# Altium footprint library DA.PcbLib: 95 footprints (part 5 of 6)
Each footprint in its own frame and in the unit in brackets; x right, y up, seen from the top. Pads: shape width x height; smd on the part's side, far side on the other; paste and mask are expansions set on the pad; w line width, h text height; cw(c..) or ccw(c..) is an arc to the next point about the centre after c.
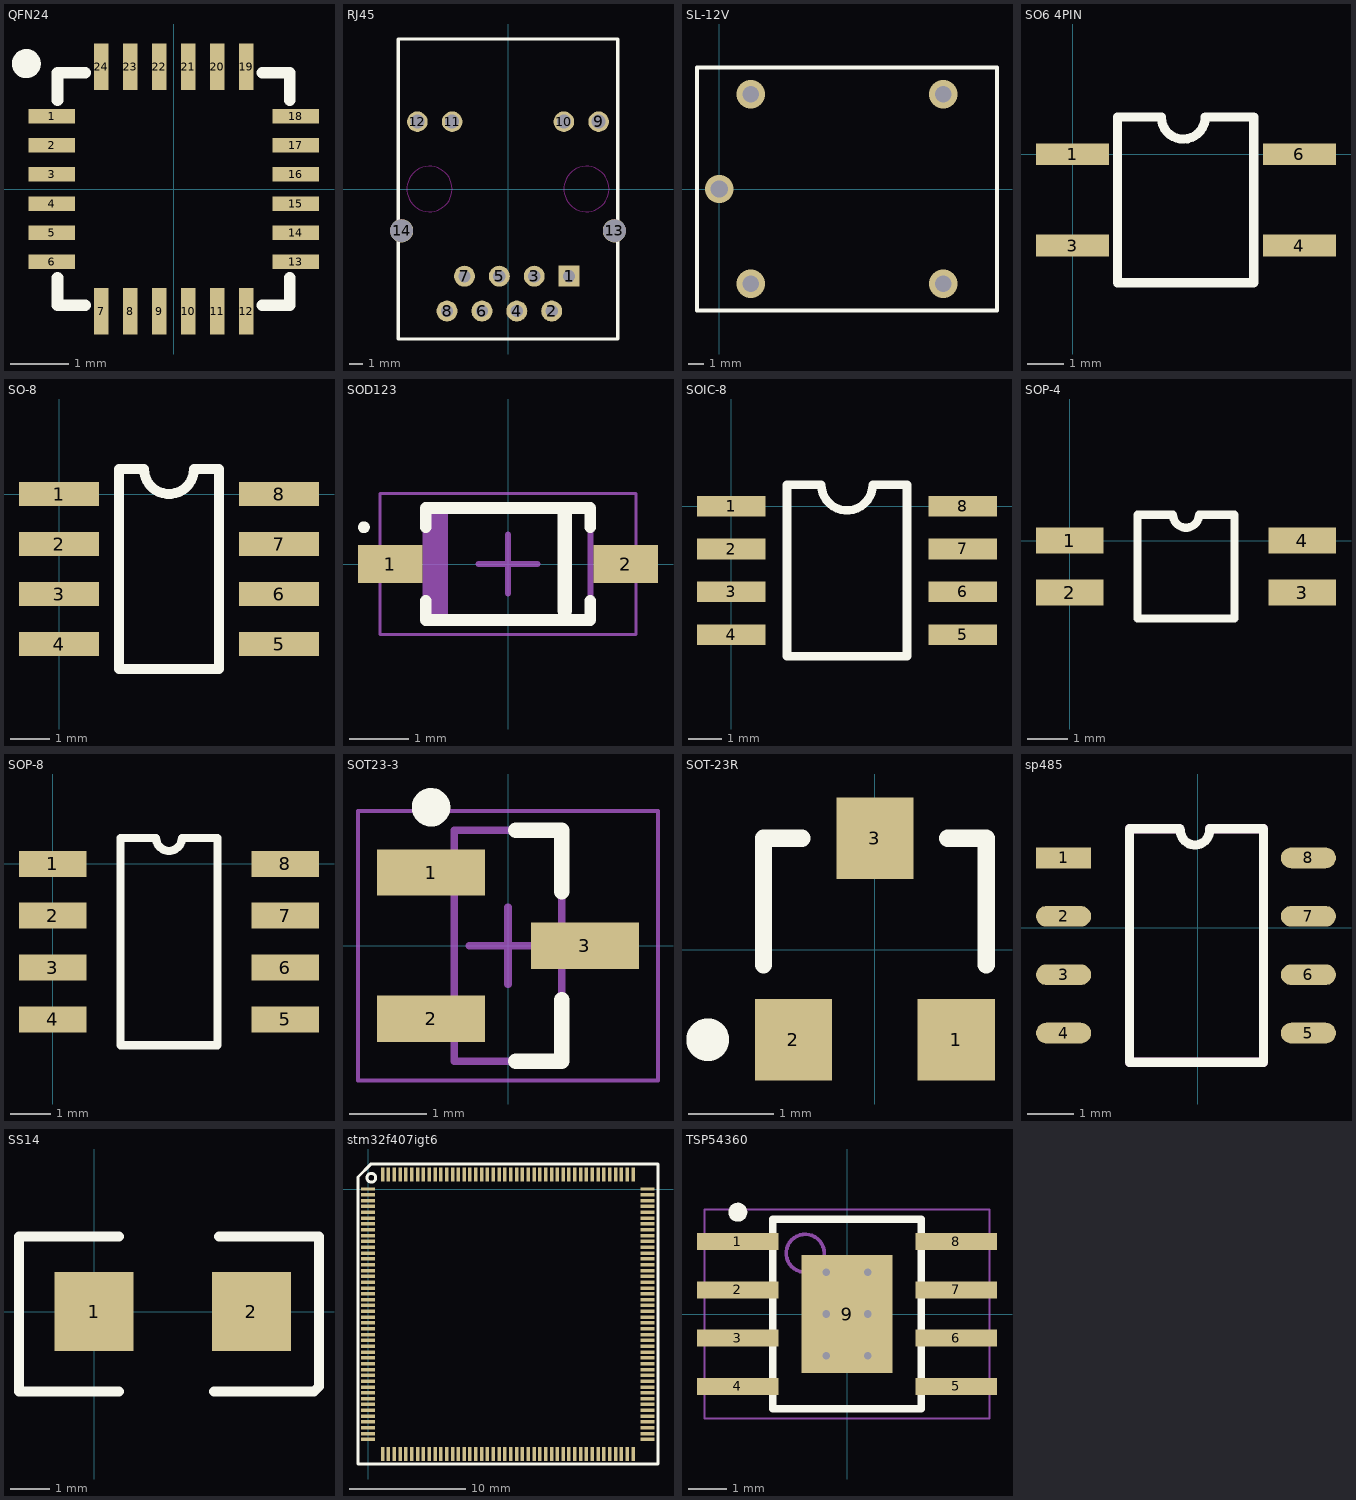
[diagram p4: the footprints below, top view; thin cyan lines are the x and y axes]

## QFN24 [mm]
pads (24):
  rect 0.8x0.25 smd: 1(-2.101,1.25) 2(-2.101,0.75) 3(-2.101,0.25) 4(-2.101,-0.25) 5(-2.101,-0.75) 6(-2.101,-1.25) 13(2.101,-1.25) 14(2.101,-0.75) 15(2.101,-0.25) 16(2.101,0.25) 17(2.101,0.75) 18(2.101,1.25)
  rect 0.25x0.8 smd: 7(-1.25,-2.101) 8(-0.75,-2.101) 9(-0.25,-2.101) 10(0.25,-2.101) 11(0.75,-2.101) 12(1.25,-2.101) 19(1.25,2.101) 20(0.75,2.101) 21(0.25,2.101) 22(-0.25,2.101) 23(-0.75,2.101) 24(-1.25,2.101)
Top Overlay:
  circle w0.25: c-2.538,2.159 r0.125
  lines w0.2: -2,-1.525 -2,-2 -1.525,-2 ; -2,1.525 -2,2 -1.525,2 ; 1.525,-2 2,-2 2,-1.525 ; 1.525,2 2,2 2,1.525

## RJ45 [mm]
height 3.8
pads (14):
  rect 1.524x1.524 hole 0.889: 1(4.45,-6.35)
  round 1.524 hole 0.889: 2(3.18,-8.89) 3(1.91,-6.35) 4(0.64,-8.89) 5(-0.63,-6.35) 6(-1.9,-8.89) 7(-3.17,-6.35) 8(-4.44,-8.89)
  round 1.5 hole 1.02: 9(6.6,4.9) 10(4.064,4.9) 11(-4.064,4.9) 12(-6.6,4.9)
  round 1.7 hole 1.65: 13(7.75,-3.048) 14(-7.75,-3.048)
Top Overlay:
  lines w0.254: -8,-10.922 0,-10.922 8,-10.922 8,10.922 0,10.922 -8,10.922 -8,-10.922
Keep-Out Layer:
  circle w0.051: c-5.714,0 r1.65
  circle w0.051: c5.716,0 r1.65

## SL-12V [mm]
via 14.2,6 diameter 1.8 hole 1.04
via 14.2,-6 diameter 1.8 hole 1.04
via 2,-6 diameter 1.8 hole 1.04
via 0,0 diameter 1.8 hole 1.1
via 2,6 diameter 1.8 hole 1.04
Top Overlay:
  lines w0.254: -1.4,-7.7 17.6,-7.7 17.6,7.7 -1.4,7.7 -1.4,-7.7

## SO6 4PIN [mil]
pads (4):
  rect 80x24 smd: 1(0,0) 3(0,-100) 4(248,-100) 6(248,0)
Top Overlay:
  lines w10: 97.03,39.29 ccw(c121,40.55) 145,40.55 198,40.55 198,-140.55 ; 97.03,40.55 49,40.55 49,-140.55 197,-140.55

## SO-8 [mil]
pads (8):
  rect 80x24 smd: 1(0,0) 2(0,-50) 3(0,-100) 4(0,-150) 5(220,-150) 6(220,-100) 7(220,-50) 8(220,0)
Top Overlay:
  lines w10: 60,-175 160,-175 160,25 135,25 cw(c110,25) 85,25 60,25 60,-175
3D body: height 63.6, standoff 0.6, extent -10.91,-172 224.91,20.91

## SOD123 [mm] "Molded Diode, 2-Leads, Body 2.65x1.60mm, IPC Medium Density"
height 1.2
pads (2):
  rect 1.1x0.65 smd: 1(-2,0) 2(2,0)
Top Overlay:
  circle w0.1: c-2.45,0.625 r0.05
  lines w0.2: -1.4,-0.625 -1.4,-0.95 1.4,-0.95 1.4,-0.625 ; -1.4,0.625 -1.4,0.95 1.4,0.95 1.4,0.625
  lines w0.254: 0.965,-0.787 0.965,0.864
Mechanical 13:
  rectangle: -1.4,-0.9 -1.023,0.9
  lines w0.1: -1.4,-0.9 -1.4,0.9 1.4,0.9 1.4,-0.9 -1.4,-0.9
Mechanical 15:
  lines w0.05: -2.175,-1.2 -2.175,1.2 2.175,1.2 2.175,-1.2 -2.175,-1.2
  lines w0.1: -0.5,0 0.5,0 ; 0,-0.5 0,0.5
3D body: height 1.2, standoff 0, extent -1.4,-0.9 1.4,0.9

## SOIC-8 [mil]
pads (8):
  rect 80x24 smd: 1(0,0) 2(0,-50.06) 3(0,-100.06) 4(0,-150.06) 5(270,-150) 6(270,-100) 7(270,-50) 8(270,0)
Top Overlay:
  lines w10: 75,24.94 75.06,25 105,25 ccw(c135,25) 165,25 204.94,25 205,24.94 205,-175.06 65,-175.06 65,24.94 95,24.94

## SOP-4 [mil]
height 149.61
pads (4):
  rect 65x25 smd: 1(0,0) 2(0,-50) 3(224.41,-50) 4(224.41,0)
Top Overlay:
  lines w7.87: 65.37,-75 65.37,25 99.7,25 ccw(c112.2,25) 124.7,25 159.04,25 159.04,-75 65.37,-75

## SOP-8 [mil]
height 149.61
pads (8):
  rect 65x25 smd: 1(0,0) 2(0,-50) 3(0,-100) 4(0,-150) 5(224.41,-150) 6(224.41,-100) 7(224.41,-50) 8(224.41,0)
Top Overlay:
  lines w7.87: 65.37,-175 159.04,-175 159.04,25 124.7,25 cw(c112.2,25) 99.7,25 65.37,25 65.37,-175

## SOT23-3 [mm] "SOT23, 3-Leads, Body 2.90x2.45mm, Pitch 0.95mm, IPC Medium Density"
height 1
pads (3):
  rect 1.4x0.6 smd: 1(-1,0.95) 2(-1,-0.95) 3(1,0)
Top Overlay:
  circle w0.25: c-1,1.8 r0.125
  lines w0.2: 0.1,-1.5 0.7,-1.5 0.7,-0.7 ; 0.1,1.5 0.7,1.5 0.7,0.7
Mechanical 13:
  lines w0.1: -0.7,-1.5 -0.7,1.5 0.7,1.5 0.7,-1.5 -0.7,-1.5
Mechanical 15:
  lines w0.05: -1.95,-1.75 -1.95,1.75 1.95,1.75 1.95,-1.75 -1.95,-1.75
  lines w0.1: -0.5,0 0.5,0 ; 0,-0.5 0,0.5
3D body: height 1, standoff 0.05, extent -0.7,-1.5 0.7,1.5

## SOT-23R [mm]
pads (3):
  rect 0.9x0.95 smd: 1(0.95,-1.048) 2(-0.95,-1.048) 3(0,1.302)
Top Overlay:
  circle w0.25: c-1.95,-1.048 r0.125
  lines w0.2: -1.3,-0.173 -1.3,1.302 -0.85,1.302 ; 0.85,1.302 1.3,1.302 1.3,-0.173

## sp485 [mm]
pads (8):
  rect 1.2x0.45 smd: 1(-2.921,1.524)
  oval 1.2x0.45 smd: 2(-2.921,0.254) 3(-2.921,-1.016) 4(-2.921,-2.286) 5(2.404,-2.286) 6(2.404,-1.016) 7(2.404,0.254) 8(2.404,1.524)
Top Overlay:
  lines w0.2: -0.381,2.124 ccw(c-0.064,2.124) 0.254,2.124
Top Overlay keep-out:
  lines w0.2: -0.396,2.159 -1.486,2.159 -1.486,-2.921 1.429,-2.921 1.429,2.159 0.254,2.159

## SS14 [mm]
pads (2):
  rect 2x2 smd: 1(0,0) 2(4,0)
Top Overlay:
  lines w0.254: 0.635,-2.032 -1.905,-2.032 -1.905,1.905 0.635,1.905 ; 3.048,-2.032 5.588,-2.032 5.715,-1.905 5.715,1.905 3.175,1.905

## stm32f407igt6 [mm]
pads (176):
  rect 1.2x0.3 smd: 1(0,0) 2(0,-0.5) 3(0,-1) 4(0,-1.5) 5(0,-2) 6(0,-2.5) 7(0,-3) 8(0,-3.5) 9(0,-4) 10(0,-4.5) 11(0,-5) 12(0,-5.5) 13(0,-6) 14(0,-6.5) 15(0,-7) 16(0,-7.5) 17(0,-8) 18(0,-8.5) 19(0,-9) 20(0,-9.5) 21(0,-10) 22(0,-10.5) 23(0,-11) 24(0,-11.5) 25(0,-12) 26(0,-12.5) 27(0,-13) 28(0,-13.5) 29(0,-14) 30(0,-14.5) 31(0,-15) 32(0,-15.5) 33(0,-16) 34(0,-16.5) 35(0,-17) 36(0,-17.5) 37(0,-18) 38(0,-18.5) 39(0,-19) 40(0,-19.5) 41(0,-20) 42(0,-20.5) 43(0,-21) 44(0,-21.5) 89(24,-21.5) 90(24,-21) 91(24,-20.5) 92(24,-20) 93(24,-19.5) 94(24,-19) 95(24,-18.5) 96(24,-18) 97(24,-17.5) 98(24,-17) 99(24,-16.5) 100(24,-16) 101(24,-15.5) 102(24,-15) 103(24,-14.5) 104(24,-14) 105(24,-13.5) 106(24,-13) 107(24,-12.5) 108(24,-12) 109(24,-11.5) 110(24,-11) 111(24,-10.5) 112(24,-10) 113(24,-9.5) 114(24,-9) 115(24,-8.5) 116(24,-8) 117(24,-7.5) 118(24,-7) 119(24,-6.5) 120(24,-6) 121(24,-5.5) 122(24,-5) 123(24,-4.5) 124(24,-4) 125(24,-3.5) 126(24,-3) 127(24,-2.5) 128(24,-2) 129(24,-1.5) 130(24,-1) 131(24,-0.5) 132(24,0)
  rect 0.3x1.2 smd: 45(1.25,-22.75) 46(1.75,-22.75) 47(2.25,-22.75) 48(2.75,-22.75) 49(3.25,-22.75) 50(3.75,-22.75) 51(4.25,-22.75) 52(4.75,-22.75) 53(5.25,-22.75) 54(5.75,-22.75) 55(6.25,-22.75) 56(6.75,-22.75) 57(7.25,-22.75) 58(7.75,-22.75) 59(8.25,-22.75) 60(8.75,-22.75) 61(9.25,-22.75) 62(9.75,-22.75) 63(10.25,-22.75) 64(10.75,-22.75) 65(11.25,-22.75) 66(11.75,-22.75) 67(12.25,-22.75) 68(12.75,-22.75) 69(13.25,-22.75) 70(13.75,-22.75) 71(14.25,-22.75) 72(14.75,-22.75) 73(15.25,-22.75) 74(15.75,-22.75) 75(16.25,-22.75) 76(16.75,-22.75) 77(17.25,-22.75) 78(17.75,-22.75) 79(18.25,-22.75) 80(18.75,-22.75) 81(19.25,-22.75) 82(19.75,-22.75) 83(20.25,-22.75) 84(20.75,-22.75) 85(21.25,-22.75) 86(21.75,-22.75) 87(22.25,-22.75) 88(22.75,-22.75) 133(22.75,1.25) 134(22.25,1.25) 135(21.75,1.25) 136(21.25,1.25) 137(20.75,1.25) 138(20.25,1.25) 139(19.75,1.25) 140(19.25,1.25) 141(18.75,1.25) 142(18.25,1.25) 143(17.75,1.25) 144(17.25,1.25) 145(16.75,1.25) 146(16.25,1.25) 147(15.75,1.25) 148(15.25,1.25) 149(14.75,1.25) 150(14.25,1.25) 151(13.75,1.25) 152(13.25,1.25) 153(12.75,1.25) 154(12.25,1.25) 155(11.75,1.25) 156(11.25,1.25) 157(10.75,1.25) 158(10.25,1.25) 159(9.75,1.25) 160(9.25,1.25) 161(8.75,1.25) 162(8.25,1.25) 163(7.75,1.25) 164(7.25,1.25) 165(6.75,1.25) 166(6.25,1.25) 167(5.75,1.25) 168(5.25,1.25) 169(4.75,1.25) 170(4.25,1.25) 171(3.75,1.25) 172(3.25,1.25) 173(2.75,1.25) 174(2.25,1.25) 175(1.75,1.25) 176(1.25,1.25)
Top Overlay:
  circle w0.254: c0.279,0.965 r0.378
  lines w0.254: -0.864,-23.597 24.892,-23.597 24.892,2.134 0.229,2.134 -0.864,1.041 -0.864,-23.597

## TJA1050 [mm]

## TSP54360 [mm] "SOP, 8-Leads, Body 4.90x3.90mm, Pitch 1.27mm, Thermal Pad 3.10.2x2.40.2mm, IPC Medium Density"
height 1.7
pads (9):
  rect 2.15x0.45 smd: 1(-2.875,1.905) 2(-2.875,0.635) 3(-2.875,-0.635) 4(-2.875,-1.905) 5(2.875,-1.905) 6(2.875,-0.635) 7(2.875,0.635) 8(2.875,1.905)
  rect 2.4x3.1 smd: 9(0,0)
via -0.55,1.1 diameter 0.5 hole 0.2
via 0.55,1.1 diameter 0.5 hole 0.2
via -0.55,0 diameter 0.5 hole 0.2
via 0.55,0 diameter 0.5 hole 0.2
via -0.55,-1.1 diameter 0.5 hole 0.2
via 0.55,-1.1 diameter 0.5 hole 0.2
Top Overlay:
  circle w0.25: c-2.875,2.68 r0.125
  lines w0.2: -1.95,-2.5 -1.95,2.5 1.95,2.5 1.95,-2.5 -1.95,-2.5
Mechanical 13:
  circle w0.1: c-1.1,1.6 r0.5
  lines w0.1: -2,-2.5 -2,2.5 2,2.5 2,-2.5 -2,-2.5
Mechanical 15:
  lines w0.05: -3.75,-2.75 -3.75,2.75 3.75,2.75 3.75,-2.75 -3.75,-2.75
  lines w0.1: -0.5,0 0.5,0 ; 0,-0.5 0,0.5
3D body: height 1.7, standoff 0.25, extent -2,-2.5 2,2.5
